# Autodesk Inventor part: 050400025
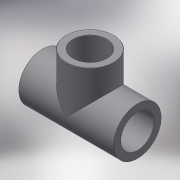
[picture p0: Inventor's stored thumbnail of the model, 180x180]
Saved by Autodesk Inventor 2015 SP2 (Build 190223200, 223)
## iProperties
Created: 2017-10
Part Number: 050400025
Material: Generic
Description: PLASSON TEE-CEMENT PVC 25
Document SubType Name: Modeling
Designer: KIM
Density: 1 g/cm^3
Appearance: Default
Author: KIM
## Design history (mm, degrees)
derived "050400.ipt"
feature "Solid1::050400.ipt"
feature "Solid2::050400.ipt"
tag "TaggingFeature1"
body "Solid1"
other parameters: "d0" = 65, "d2" = 19, "d4" = 25, "d5" = 22.5, "d7" = 0.25, "d8" = 19, "d9" = 33, "d11" = 25, "d12" = 22.5, "d15" = 0, "d17" = 0, "d18" = 25, "d19" = 22.5, "d20" = 25, "d21" = 19, "d22" = 0, "d23" = 19, "d24" = 0.25, "d_" = 25, "H_" = 65, "l_" = 19, "Z_" = 14
